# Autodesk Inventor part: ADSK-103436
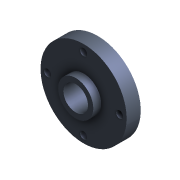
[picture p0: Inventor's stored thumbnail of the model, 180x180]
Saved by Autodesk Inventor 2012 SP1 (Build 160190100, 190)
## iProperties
Shininess: 0.0
Created: 2000-11
Part Number: ADSK-103436
Description: MFC - 28    SEALMASTER
Document SubType Name: Modeling
Stock Number: ADSK-103436
Density: 1 g/cm^3
Material: Default
Density: 0.0
Volumn: 0.0
Area: 0.0
PropertySet Name: Model Information
Control State: 0
Master: False
Checked Out: False
Author: gao
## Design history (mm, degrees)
node "Extrusion1" dims "d2" = 51.6128, "d3" = 0
  sketch "Sketch1"
    geometry: C1 r 77.788 at (0, 0); C2 r 22.225 at (0, 0)
    constraints: 2 centre point, 1 coincident
    dimensions: "d0" = 44.45 diameter of C2; "d1" = 155.575 diameter of C1
node "Extrusion2" dims "d5" = 14.224, "d6" = 0
  sketch "Sketch2"
    geometry: C1 r 77.788 at (0, 0) reference; C2 r 31.75 at (0, 0)
    constraints: 1 centre point, 1 coincident
    dimensions: "d4" = 63.5 diameter of C2
node "Extrusion3" dims "d8" = 11.90625, "d9" = 0
  sketch "Sketch3"
    geometry: C1 r 77.788 at (0, 0) reference; C2 r 53.975 at (0, 0)
    constraints: 1 centre point, 1 coincident
    dimensions: "d7" = 107.95 diameter of C2
node "Hole1" dims "d11" = 12.7, "d12" = 9.525, "d13" = 6.35, "d14" = 60 deg, "d15" = 19.05, "d16" = 118 deg
  sketch "Sketch4" dims "d10" = 130.175
    geometry: C1 r 77.788 at (0, 0) reference; 2 further points
    constraints: 1 coincident, 1 vertical alignment, 2 other
node "Circular Pattern1" dims "d17" = 40, "d19" = 90 deg
body "Solid1"
